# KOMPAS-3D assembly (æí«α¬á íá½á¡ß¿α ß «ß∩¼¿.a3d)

Referenced files in D:\МОДЕЛЬ ТАНКА Т90\ДЕТАЛИ\ХОДОВАЯ\Каток опорный с балансиром\: балансир.m3d, ось балансира.m3d, ось катка.m3d
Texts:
  Сборка балансир с осями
